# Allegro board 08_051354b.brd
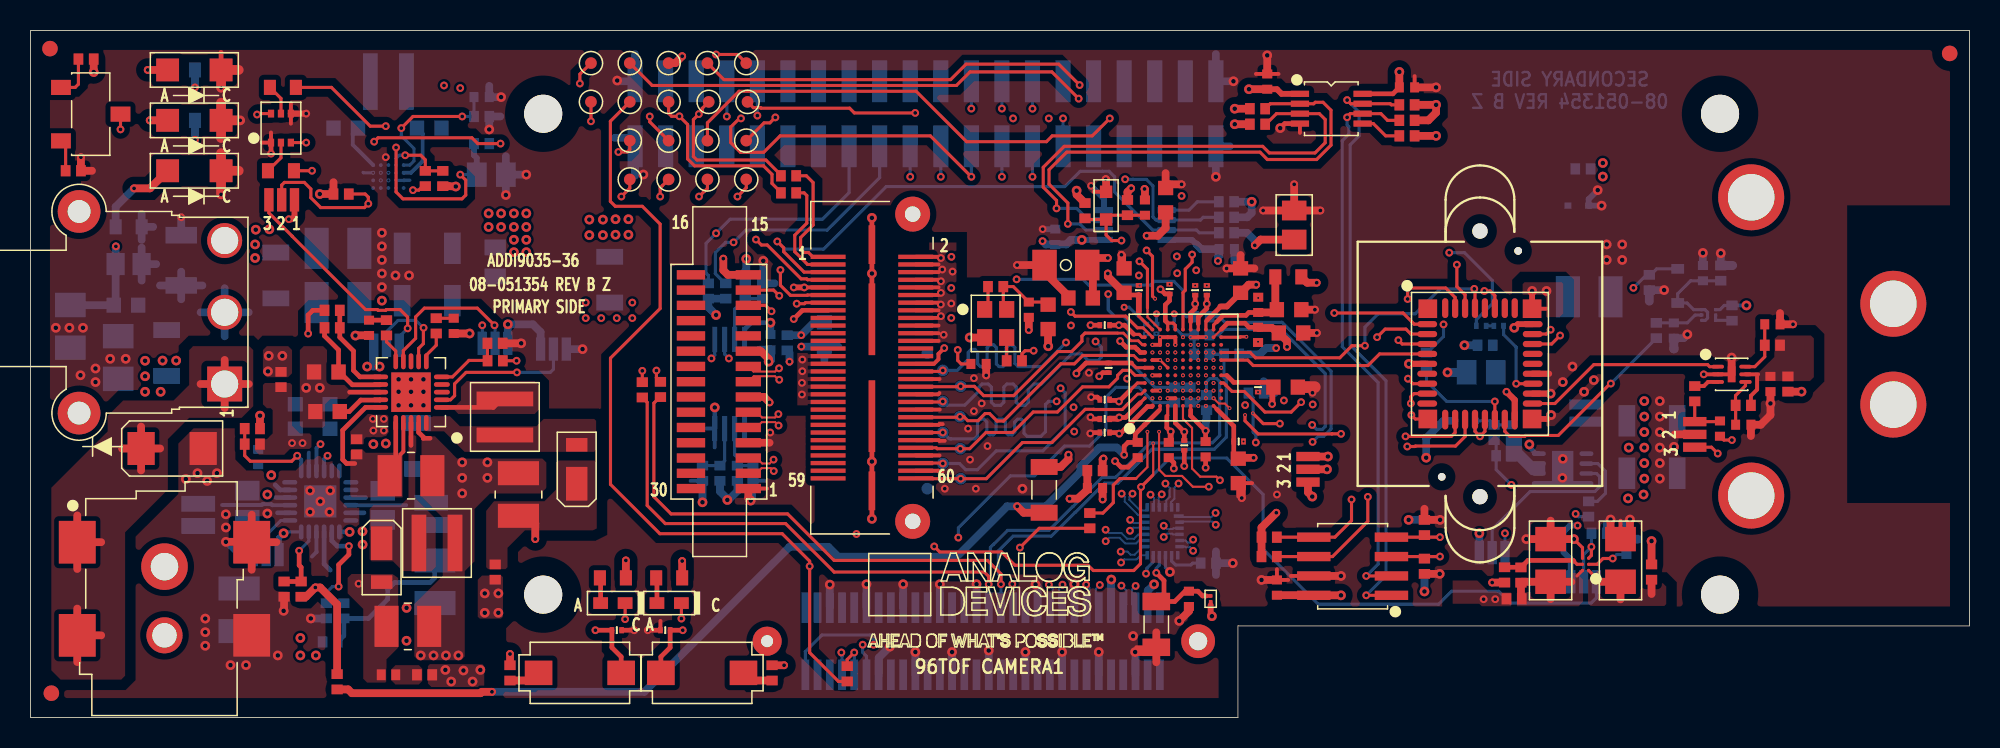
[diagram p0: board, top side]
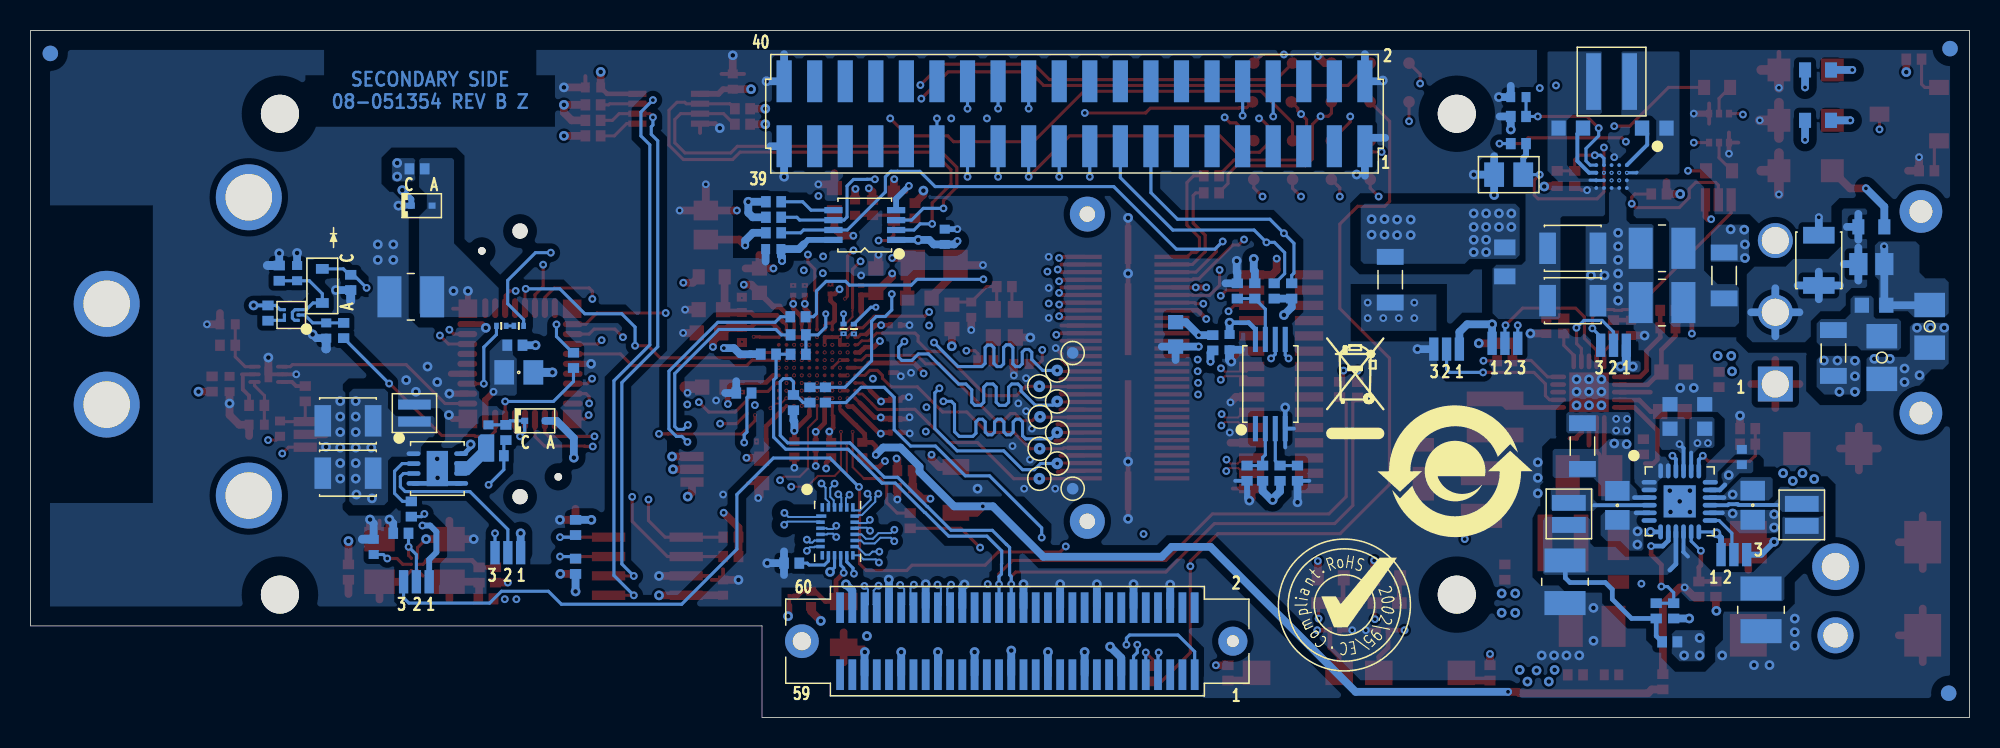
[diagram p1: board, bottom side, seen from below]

Outline 126.86 x 45 mm; copper layers: TOP, L2_GND, L3_SIG, L4_GND, L5_PWR, L6_PWR, L7_GND, L8_SIG, L9_GND, BOTTOM. Coordinates in mm from the lower left corner of the outline.
Outline path: 0,45 126.86,45 126.86,6 79,6 79,0 0,0 0,45

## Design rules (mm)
constraint set DEFAULT: min track width 0.203, pair gap 0.203
net group DP1: nets CCDGNDA CCDINA
net group CLK_DATA_MISIPI: nets CLK_N CLK_P DATA0_N DATA0_P DATA1_N DATA1_P
net group LD1_LD4: nets LD1 LD2 LD3 LD4
net group MIPI_DATA_P3_CONN: nets MIPI_CSI1_CLK_M MIPI_CSI1_CLK_P MIPI_CSI1_DATA0_M MIPI_CSI1_DATA0_P MIPI_CSI1_DATA1_M MIPI_CSI1_DATA1_P
net group RPI_DATA_P1_CONN: nets RPI_CLKN RPI_CLKP RPI_DATA0N RPI_DATA0P RPI_DATA1N RPI_DATA1P
net group TAL1_TAL4: nets TAL1 TAL2 TAL3 TAL4

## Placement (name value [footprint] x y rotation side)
A1  ADA4800_PRELIM  [UQFN6_1_6X1_6PAD0_5X1_05]  111.3 22.48 270 top
C1  2.2UF  [C1206]  73.66 6.1 90 top
C2  0.1uF  [C0201]  73.67 25.45 270 bottom
C3  4.7UF  [C0805H60]  14.18 13.91 90 bottom
C4  4.7UF  [C0805H60]  23.04 13.89 270 bottom
C5  0.1UF  [C0402]  65.31 26.71 270 top
C6  4.7uF  [C0603]  74.27 33.88 90 top
C7  0.1UF  [C0402]  69.64 15.03 0 top
C8  0.1uF  [C0201]  72.99 25.45 270 bottom
C9  0.1UF  [C0402]  14.89 17.06 270 bottom
C10  4.7uF  [C0603]  68.7 27.48 180 top
C11  4.7uF  [C0603]  79.17 28.62 90 top
C12  4.7uF  [C0603]  82.47 25.19 0 top
C13  1UF  [C0805H53]  82.68 32.26 90 top
C14  0.1uF  [C0201]  70.53 22.9 270 top
C15  0.1UF  [C0402]  80.31 25.06 270 top
C16  0.1uF  [C0201]  70.28 20.82 180 top
C17  0.1uF  [C0201]  76.96 27.98 90 top
C18  1000PF  [C0402]  107.51 25.35 270 bottom
C19  0.1uF  [C0201]  75.49 17.82 270 top
C20  4.7uF  [C0603]  82.34 26.71 180 top
C21  0.1UF  [C0402]  110.54 18.92 270 top
C22  0.1uF  [C0201]  80.31 21.63 270 top
C23  0.1uF  [C0201]  70.28 18.66 180 top
C24  0.1UF  [C0402]  62.02 23.16 0 top
C25  0.1uF  [C0201]  79.04 18.08 0 top
C26  0.1uF  [C0201]  70.28 25.7 180 top
C27  0.1UF  [C0402]  80.32 27.03 90 top
C28  0.1uF  [C0201]  72.51 27.98 90 top
C29  0.1UF  [C0402]  113.97 25.76 180 top
C30  0.01uF  [C0402]  109.42 29.11 90 bottom
C31  0.1uF  [C0201]  70.28 19.55 180 top
C32  22UF  [C1210H106]  25.95 30.73 180 bottom
C33  0.1UF  [C0402]  76.88 17.57 270 top
C34  22UF  [C1210H106]  25.95 27.3 180 bottom
C35  1000PF  [C0402]  29.51 40.64 0 bottom
C36  0.1uF  [C0603]  20.62 38.61 0 bottom
C37  0.1uF  [C0603]  26.08 38.61 0 bottom
C38  10uF  [C1210-2]  20.11 27.18 0 bottom
C39  10uF  [C1210-2]  20.11 30.73 0 bottom
C40  1UF  [C0805H53]  30.15 35.56 0 bottom
C41  10uF  [C1210-2]  24.89 15.84 0 top
C42  22UF  [C1210H106]  9.86 29.95 90 bottom
C43  1UF  [C0603]  19.35 22.63 180 top
C44  22UF  [C1210H106]  106.09 16 0 bottom
C45  1UF  [C0603]  19.59 19.72 90 bottom
C46  1UF  [C0603]  17.32 19.72 90 bottom
C47  10uF  [C1210-2]  26.46 8.89 270 bottom
C48  10uF  [C1210-2]  13.64 7.05 270 bottom
C49  10UF  [C1206H71]  2.6 25.62 90 bottom
C50  10UF  [C1206H71]  5.73 23.58 90 bottom
C51  10uF  [C1210-2]  101.98 27.56 0 bottom
C52  0.1UF  [C0402]  48.41 24.59 270 bottom
C53  1uF  [C0402]  72.44 17.52 90 top
C54  1uF  [C0402]  74.47 17.52 270 top
C55  0.10UF  [C0508H28]  101.74 19.94 90 bottom
C56  10NF  [C0402]  75.79 7.77 90 top
C57  1uF  [C0402]  72.91 33.4 270 top
C58  0.1uF  [C0201]  76.2 27.98 90 top
C59  0.033uF  [C0402]  96.9 18.67 90 bottom
C60  0.1uF  [C0201]  74.52 28.06 90 top
C61  10UF  [C1206H71]  67.74 29.64 180 top
C62  0.1UF  [C0402]  113.84 21.84 90 top
C63  0.1UF  [C0402]  80.91 41.66 270 top
C64  22UF  [C1210H106]  106.09 19.43 0 bottom
C65  0.1UF  [C0402]  112.06 19.18 0 top
C66  1UF  [C0603]  19.43 20.04 180 top
C67  0.1uF  [C0603]  51.94 25.1 90 bottom
C68  0.1UF  [C0402]  90.06 41.27 0 top
C69  0.1UF  [C0402]  81.55 8.51 270 top
C70  0.1UF  [C0402]  67.04 31.49 270 bottom
C71  10uF  [C1210-2]  24.68 5.97 0 top
C72  0.047UF  [C0402]  27.69 25.65 270 top
C73  0.01uF  [C0201]  96.06 25.65 0 bottom
C74  0.047UF  [C0402]  22.14 25.53 270 top
C75  0.1UF  [C0402]  78.26 30.68 0 bottom
C76  4.7UF  [C0805H60]  94.92 22.61 180 bottom
C77  0.01uF  [C0603]  79.02 16.15 90 top
C78  10uF  [C1210-2]  31.92 14.61 90 top
C79  2.2uF  [C1206H37]  104.03 10.29 90 top
C80  1000PF  [C0402]  104.41 11.18 90 bottom
C81  2.2uF  [C1206H37]  99.45 10.29 90 top
C82  0.01uF  [C0603]  82.12 21.64 180 top
C83  0.01uF  [C0603]  71.55 28.62 270 top
C84  0.01uF  [C0201]  38.35 5.71 0 top
C85  0.01uF  [C0201]  41.53 5.71 180 top
D1  SMAJ5.0A  [DO214AC]  9.26 17.62 0 top
D4  RB521S30T1G  [SOD523]  93.85 19.43 180 bottom
D5  1SS355VMTE-17  [SOD323-4]  107.77 28.27 270 bottom
D6  RB521S30T1G  [SOD523]  101.27 33.53 180 bottom
D8  DFLS240-7  [DSML110W70H39]  22.97 10.47 270 top
D9  DFLS240-7  [DSML110W70H39]  35.73 16.26 90 top
DS1  CMD15-21UGC/TR8 (green)  [LED1206]  10.71 35.81 180 top
DS2  CMD15-21UGC/TR8 (green)  [LED1206]  10.71 39.12 180 top
DS3  CMD15-21UGC/TR8 (green)  [LED1206]  10.71 42.42 180 top
DS4  APT1608LVBC/D  [LED0603]  38.1 7.49 180 top
DS5  APT1608LSECK/J3-PRV  [LED0603]  41.78 7.49 180 top
E1  60OHM AT 100MEGHZ  [L0603]  66.57 26.24 270 top
E2  22OHM AT 100MEGHZ  [L0805]  6.42 29.7 180 bottom
E3  30OHM  [L0603]  6.24 27.01 0 bottom
E4  470OHMS AT 100MEGHZ  [L0402]  23.42 2.79 0 top
E5  22OHM AT 100MHZ  [L01005]  77.21 7.77 90 top
GND7  TESTPAD  [TPSMC30]  58.67 14.99 270 bottom
GND8  TESTPAD  [TPSMC30]  58.67 23.88 270 bottom
JP1  3PIN_SOLDER_JUMPER  [JPRSLD03]  83.58 16.26 270 top
JP2  3PIN_SOLDER_JUMPER  [JPRSLD03]  95.63 10.79 0 bottom
JP3  3PIN_SOLDER_JUMPER  [JPRSLD03]  16.43 33.91 180 top
JP4  3PIN_SOLDER_JUMPER  [JPRSLD03]  15.41 10.67 180 bottom
JP5  3PIN_SOLDER_JUMPER  [JPRSLD03]  108.89 18.54 270 top
JP6  3PIN_SOLDER_JUMPER  [JPRSLD03]  30.39 24.51 180 bottom
JP7  3PIN_SOLDER_JUMPER  [JPRSLD03]  23.29 24.38 0 bottom
JP8  3PIN_SOLDER_JUMPER  [JPRSLD03]  34.21 24.13 0 bottom
JP9  3PIN_SOLDER_JUMPER  [JPRSLD03]  101.61 8.89 0 bottom
L1  2.2uH  [LSMSQ157H83_A]  23.41 41.66 180 bottom
L2  1uH  [LSML75W79H39]  10.97 13.27 90 bottom
L3  1uH  [LSML75W79H39]  26.21 13.34 90 bottom
L8  4.7uH  [LSMSQ157H122]  26.59 11.43 180 top
L9  4.7uH  [LSMSQ157H122]  31.03 19.68 270 top
LD1  TESTPAD  [TPSMC30]  60.86 15.64 270 bottom
LD2  TESTPAD  [TPSMC30]  60.84 17.61 270 bottom
LD3  TESTPAD  [TPSMC30]  60.81 19.7 270 bottom
LD4  TESTPAD  [TPSMC30]  60.86 21.69 270 bottom
LD_EN1  0  [R0402]  49.59 35.48 180 top
LD_EN2  0  [R0402]  49.59 34.37 180 top
NOREF  -  []  0 45 0 top
NOREF#2  -  []  -176.26 -281.43 0 top
NOREF#3  -  []  0 0 0 top
NOREF#4  -  []  79 0 0 top
NOREF#5  -  []  70.12 -90.11 0 top
NOREF#6  -  [unnamed#2]  110.54 39.55 0 top
NOREF#7  -  []  -176.26 -281.43 0 top
NOREF#8  -  [unnamed#2]  1.27 43.81 90 top
NOREF#9  -  []  -176.26 -281.43 0 top
NOREF#10  -  []  -10.16 55.16 0 top
NOREF#11  -  []  8.76 5.38 0 top
NOREF#12  -  []  57.78 56.26 0 top
NOREF#13  -  []  281.83 80.52 0 top
NOREF#14  -  [unnamed#2]  33.54 39.55 0 top
NOREF#15  -  [unnamed#2]  33.54 8.05 0 top
NOREF#16  -  [unnamed#3]  94.83 23.16 270 top
NOREF#17  -  []  79 0 90 top
NOREF#18  -  []  0 0 0 top
NOREF#19  -  []  79 6 0 top
NOREF#20  -  [unnamed#2]  125.57 43.5 90 top
NOREF#21  -  []  8.76 5.38 0 top
NOREF#22  -  []  126.86 6 0 top
NOREF#23  -  []  -125.84 190.5 0 top
NOREF#24  -  []  332.25 207.39 0 top
NOREF#25  -  [unnamed#2]  121.88 27.1 90 top
NOREF#26  -  []  137.02 55.16 0 top
NOREF#27  -  [unnamed#2]  121.88 20.5 90 top
NOREF#28  -  [unnamed#2]  110.54 8.05 0 top
NOREF#29  -  []  0 45 0 top
NOREF#30  -  [unnamed#2]  1.36 1.59 90 top
NOREF#31  -  [unnamed#2]  112.58 14.54 90 top
NOREF#32  -  [unnamed#2]  112.58 34.08 90 top
NOREF#33  -  [unnamed#2]  1.27 43.81 90 bottom
NOREF#34  -  [unnamed#2]  1.36 1.59 90 bottom
NOREF#35  -  []  -10.16 -10.16 180 bottom
NOREF#36  -  []  40.39 18.29 180 bottom
NOREF#37  -  [unnamed#2]  125.57 43.5 90 bottom
NOREF#38  -  []  79 6 0 bottom
NOREF#39  -  []  0 0 90 bottom
NOREF#40  -  []  0 45 0 bottom
NOREF#41  -  []  126.86 45 270 bottom
NOREF#42  -  []  126.86 6 180 bottom
NOREF#43  -  []  33.66 16.13 180 bottom
NOREF#44  -  []  40.89 7.37 180 bottom
NOREF#45  -  []  79 0 180 bottom
P1  1-1734248-5  [CNTE1-1734248-5]  45.09 22 90 top
P3  61083-063402LF  [CNFCI61083-063402]  62.29 5 0 bottom
P4  87759-4014  [CNSMMHDR2X20L1571W157H272]  58.55 39.55 0 bottom
P21  QSH-030-01-L-D-A  [CNHDR2X30H202]  55.05 22.91 270 top
P31  PJ-002AH-SMT-TR  [CNCUI-PJ-002A_A]  8.76 7.78 0 top
Q1  DST847BPDP6-7  [SOT-963]  109.8 26.37 90 bottom
Q2  BC847CDW1T1G  [SC70]  16.38 38.61 0 top
R1  10K  [R0402]  63.15 28.22 0 top
R2  49.9  [R0402]  80.19 21.25 180 bottom
R3  0  [R0402]  76.63 25.06 180 bottom
R4  0  [R1206]  66.32 14.91 90 top
R5  0  [R0402]  101.94 13.66 90 bottom
R6  0  [R0402]  76.63 23.79 180 bottom
R7  47  [R0402]  106.37 25.35 90 bottom
R8  0  [R0402]  30.4 9.53 270 top
R9  0  [R0402]  114.98 21.84 90 top
R10  0  [R0603]  82.29 28.86 180 top
R11  0  [R0805]  30.4 29.84 270 bottom
R12  0  [R0402]  25.83 35.31 90 top
R13  100K  [R0402]  29.51 39.37 0 bottom
R14  10K  [R0402]  20.32 34.29 180 top
R15  100K  [R0402]  29.51 37.59 180 bottom
R16  0  [R1206]  16.05 28.96 90 bottom
R17  0  [R1206]  25.32 17.78 270 bottom
R18  10K  [R0402]  14.51 18.92 180 top
R19  26.7K  [R0402]  14.51 17.91 0 top
R20  29.4K  [R0402]  19.35 6.99 270 bottom
R21  95.3K  [R0402]  20.49 6.99 270 bottom
R22  0  [R0402]  20.06 2.34 270 top
R23  19.1K  [R0402]  16.59 8.41 270 top
R24  0  [R0402]  78.25 33.78 180 bottom
R25  0  [R0402]  26.97 35.31 270 top
R26  1K  [R0402]  111.32 26.49 270 bottom
R27  5.1K  [R0402]  110.59 29.11 90 bottom
R28  0  [R0402]  74.85 21.13 90 bottom
R29  1MEG  [R0402]  105.91 28.5 270 bottom
R30  115K  [R0402]  17.7 8.41 270 top
R31  120K  [R0402]  113.97 24.38 0 top
R32  0  [R0402]  19.6 4.95 180 bottom
R33  249K  [R0402]  112.06 20.45 0 top
R34  0  [R0402]  16.38 22.14 90 top
R35  0  [R0402]  49.51 24.54 270 bottom
R36  0  [R0402]  2.79 35.81 180 top
R37  220  [R0603]  38.1 9.14 0 top
R38  10K  [R0402]  102.63 12.06 0 bottom
R39  0  [R1206]  37.9 28.68 270 bottom
R40  49.9  [R0402]  96.39 17.14 0 bottom
R41  0  [R0402]  75.87 21.13 90 bottom
R42  0  [R0402]  95.76 18.67 270 bottom
R43  10K  [R0402]  76.94 20.63 90 bottom
R44  0  [R0402]  21.34 17.73 270 top
R45  10K  [R0402]  78.58 23.8 180 bottom
R46  147K  [R0402]  19.73 25.53 0 top
R47  0  [R0402]  45.11 16 270 bottom
R48  137K  [R0402]  30.39 24.51 0 top
R49  1.2MEG  [R0402]  19.73 26.67 180 top
R50  24.9K  [R0402]  26.54 25.65 90 top
R51  6.8K  [R0402]  23.29 25.53 90 top
R52  2.37MEG  [R0402]  30.4 23.37 0 top
R53  0  [R0402]  25.78 2.79 0 top
R54  0  [R0402]  43.96 16 90 bottom
R55  0  [R0402]  46.76 27.94 90 bottom
R56  0  [R0402]  106.06 9.53 270 top
R57  14.3K  [R0402]  96.44 9.34 270 top
R58  93.1K  [R0402]  97.51 9.33 270 top
R59  0  [R0402]  97.07 7.77 180 top
R60  0  [R0402]  47.9 27.94 270 bottom
R61  22K  [R0402]  44.34 27.94 270 bottom
R62  0  [R0402]  46.25 16 270 bottom
R63  0  [R0402]  47.27 16 90 bottom
R64  22K  [R0402]  45.49 27.94 270 bottom
R65  0  [R0402]  69.64 16.17 0 top
R66  4.7  [R0402]  91.33 23.39 270 bottom
R67  22K  [R0402]  80.28 38.86 180 top
R68  22K  [R0402]  80.28 39.88 180 top
R69  4.7  [R0201]  94.92 25.65 0 bottom
R70  0  [R0402]  101.57 35.94 0 bottom
R71  0  [R0402]  95.17 24.38 180 bottom
R72  45.3K  [R0402]  68.99 33.2 90 top
R73  45.3K  [R0402]  71.77 33.4 270 top
R74  4.7K  [R0402]  90.06 39.12 180 top
R75  300  [R0603]  41.78 9.14 180 top
R76  0  [R0402]  108.89 21.21 270 top
R77  100K  [R0402]  31.37 2.92 270 top
R78  10K  [R0603]  16.38 35.81 180 top
R79  10K  [R0603]  16.51 41.27 180 top
R80  100K  [R0402]  48.51 2.92 270 top
R82  4.7K  [R0402]  90.06 40.13 180 top
R86  10K  [R0402]  81.04 11.81 0 top
R87  10K  [R0402]  81.04 10.54 0 top
R88  0  [R0402]  76.65 26.25 0 bottom
R89  0  [R0402]  69.31 12.89 270 top
R90  0  [R0402]  77.06 10.11 180 bottom
R91  0  [R0402]  3.63 43.13 0 top
R93  4.7K  [R0402]  78.25 32.77 0 bottom
R94  4.7K  [R0402]  78.25 31.75 0 bottom
R95  0  [R1206]  8.9 23.88 270 bottom
R98  0  [R0402]  40.03 21.46 90 top
R100  150  [R0603]  6.42 32.14 0 bottom
R101  0  [R0402]  90.06 38.1 0 top
R102  0  [R0402]  91.2 12.45 90 bottom
R103  0  [R0402]  91.2 12.45 270 top
R104  680  [R0603]  9.91 39.12 180 bottom
R105  0  [R0402]  91.2 9.91 270 bottom
R106  0  [R0402]  91.2 9.91 90 top
R108  220  [R0603]  9.91 42.42 0 bottom
R109  0  [R0402]  41.21 21.49 90 top
R110  22  [R0402]  64.36 23.37 0 top
R113  22  [R0402]  53.43 2.86 90 top
RT1  100K  [R0603H35]  70.37 33.53 270 top
S1  CAS-120TB  [SWSML213W98H98]  3.94 39.52 270 top
S2  MS12ASW30  [SWTHL500W272H280]  12.7 21.84 90 top
S3  SKQMBBE010  [SWSML236W138H197]  35.94 2.92 0 top
S4  SKQMBBE010  [SWSML236W138H197]  43.94 2.92 0 top
TAL1  TESTPAD  [TPSMC30]  59.69 16.64 270 bottom
TAL2  TESTPAD  [TPSMC30]  59.69 18.67 270 bottom
TAL3  TESTPAD  [TPSMC30]  59.69 20.7 270 bottom
TAL4  TESTPAD  [TPSMC30]  59.69 22.73 270 bottom
TP1  TESTPAD  [TPSMC30]  46.91 40.33 0 top
TP2  TESTPAD  [TPSMC30]  46.83 37.79 0 top
TP3  TESTPAD  [TPSMC30]  46.83 42.87 0 top
TP4  TESTPAD  [TPSMC30]  41.75 35.25 0 top
TP5  TESTPAD  [TPSMC30]  39.21 35.25 0 top
TP6  TESTPAD  [TPSMC30]  44.29 37.79 0 top
TP7  TESTPAD  [TPSMC30]  41.75 37.79 0 top
TP8  TESTPAD  [TPSMC30]  36.67 40.33 0 top
TP9  TESTPAD  [TPSMC30]  36.67 42.87 270 top
TP10  TESTPAD  [TPSMC30]  39.21 37.79 0 top
TP11  TESTPAD  [TPSMC30]  46.83 35.25 0 top
TP12  TESTPAD  [TPSMC30]  44.29 35.25 0 top
TP13  TESTPAD  [TPSMC30]  39.21 42.87 0 top
TP14  TESTPAD  [TPSMC30]  44.29 42.87 0 top
TP15  TESTPAD  [TPSMC30]  39.21 40.33 0 top
TP16  TESTPAD  [TPSMC30]  41.75 40.33 0 top
TP17  TESTPAD  [TPSMC30]  44.37 40.33 0 top
TP18  TESTPAD  [TPSMC30]  41.75 42.87 0 top
U1  MN34906BL  [QFN38_7_8X7_4]  94.83 23.16 270 top
U2  ADP2505ACBZ  [WLCSP20_A]  23.41 35.43 0 bottom
U3  ADP5023ACPZ  [QFN24_4X4_PAD2_1X2_1]  18.96 14.16 270 bottom
U4  ADDI9036BCBZRL  [WLCSP117_A]  75.4 22.91 0 top
U5  AT24CM01-XHM-B  [TSSOP8]  45.74 21.84 180 bottom
U6  FAN3121TMPX  [MLP8_3X3_PAD2_3X1_4]  100.24 16.31 270 bottom
U7  FSA642UMX  [QFN24_3_4X2_5]  74.05 12.19 270 bottom
U8  PCA9517ADMR2G  [MSOP8_ALT]  85.1 39.88 270 top
U9  PCA9517ADMR2G  [MSOP8_ALT]  72.28 32.26 90 bottom
U10  ADP5071ACPZ  [QFN20_4X4_PAD2_6X2_6]  24.89 21.31 90 top
U12  ADP7112ACBZ-1.2-R7  [WLCSP6_B]  101.74 10.03 90 top
U13  ADT7410TRZ  [SO8]  86.5 9.91 90 top
Y1  45.000000MEGHZ  [YSML98W79H35]  63.15 25.81 270 top

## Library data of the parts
A1 = ADA4800_PRELIM: User Part Number: UPN; Tolerance: N/A; alternate symbols: (); part number: ADA4800_PRELIM_SM-ADA4800_PRELIM,E012130,UQFN6_1_6X1_6PAD0_5X1_05; tolerance: N/A
C1 = CAP: User Part Number: UPN; Tolerance: 10; alternate symbols: (); part number: CAP_SM-2.2UF,16V,10,E033858,C1206; tolerance: 10
C2 C8 C14 C16 C17 C19 C22 C23 C25 C26 C28 C31 C58 C60 = CAP: Tolerance: 10; User Part Number: UPN; alternate symbols: (); part number: CAP_SM-0.1UF,6.3V,10,E011567,C0201; tolerance: 10
C3 C4 C76 = CAP: Tolerance: 10; User Part Number: UPN; alternate symbols: (); part number: CAP_SM-4.7UF,25V,10,E033894,C0805H60; tolerance: 10
C5 C7 C9 C15 C21 C24 C27 C29 C33 C52 C62 C63 C65 C68-C70 C75 = CAP: User Part Number: UPN; Tolerance: 10; alternate symbols: (); part number: CAP_SM-0.1UF,16V,10,E028141,C0402; tolerance: 10
C6 C10 C12 C20 = CAP: User Part Number: UPN; Tolerance: 10; alternate symbols: (); part number: CAP_SM-4.7UF,16V,10,E022190,C0603; tolerance: 10
C11 = CAP: User Part Number: UPN; Tolerance: 10; alternate symbols: C0603L; part number: CAP_SM-4.7UF,16V,10,E022190,C0603; tolerance: 10
C13 = CAP: Tolerance: 10; User Part Number: UPN; alternate symbols: C0805L; part number: CAP_SM-1UF,35V,10,E035216,C0805H53; tolerance: 10
C18 = CAP: User Part Number: UPN; Tolerance: 10; alternate symbols: (); part number: CAP_SM-1000PF,50V,10,E020689,C0402; tolerance: 10
C30 = CAP: User Part Number: UPN; Tolerance: 5; alternate symbols: (C0402L_ALT); part number: CAP_SM-0.01UF,25V,5,E020410,C0402; tolerance: 5
C32 C34 C42 C44 C64 = CAP: Tolerance: 10; User Part Number: UPN; alternate symbols: (); part number: CAP_SM-22UF,25V,10,E025745,C1210H106; tolerance: 10
C35 C80 = CAP: User Part Number: UPN; Tolerance: 10; alternate symbols: (); part number: CAP_SM-1000PF,25V,10,E025706,C0402; tolerance: 10
C36 C37 = CAP: User Part Number: UPN; Tolerance: 10; alternate symbols: (); part number: CAP_SM-0.1UF,50V,10,E011865,C0603; tolerance: 10
C38 C39 C41 C47 C48 C51 C71 C78 = CAP: Tolerance: 10; User Part Number: UPN; alternate symbols: (); part number: CAP_SM-10UF,50V,10,E022361,C1210-2; tolerance: 10
C40 = CAP: Tolerance: 10; User Part Number: UPN; alternate symbols: (); part number: CAP_SM-1UF,50V,10,E033068,C0805H53; tolerance: 10
C43 C45 C46 C66 = CAP: User Part Number: UPN; Tolerance: 10; alternate symbols: (); part number: CAP_SM-1UF,25V,10,E025743,C0603; tolerance: 10
C49 C50 C61 = CAP: Tolerance: 10; User Part Number: UPN; alternate symbols: (); part number: CAP_SM-10UF,25V,10,E022363,C1206H71; tolerance: 10
C53 C54 C57 = CAP: User Part Number: UPN; Tolerance: 10; alternate symbols: (); part number: CAP_SM-1UF,6.3V,10,E011561,C0402; tolerance: 10
C55 = CAP: Tolerance: 20; User Part Number: UPN; alternate symbols: (); part number: CAP_SM-0.10UF,25V,20,E025747,C0508H28; tolerance: 20
C56 = CAP: User Part Number: UPN; Tolerance: 10; alternate symbols: (); part number: CAP_SM-10NF,25V,10,E033465,C0402; tolerance: 10
C59 = CAP: User Part Number: UPN; Tolerance: 10; alternate symbols: (); part number: CAP_SM-0.033UF,50V,10,E019776,C0402; tolerance: 10
C67 = CAP: User Part Number: UPN; Tolerance: 10; alternate symbols: (); part number: CAP_SM-0.1UF,16V,10,E011547,C0603; tolerance: 10
C72 C74 = CAP: User Part Number: UPN; Tolerance: 10; alternate symbols: (); part number: CAP_SM-0.047UF,25V,10,E025704,C0402; tolerance: 10
C73 C84 C85 = CAP: Tolerance: 10; User Part Number: UPN; alternate symbols: (); part number: CAP_SM-0.01UF,10V,10,E007201,C0201; tolerance: 10
C77 C82 C83 = CAP: User Part Number: UPN; Tolerance: 5; alternate symbols: (); part number: CAP_SM-0.01UF,25V,5,E012400,C0603; tolerance: 5
C79 C81 = CAP: Tolerance: 10; User Part Number: UPN; alternate symbols: (); part number: CAP_SM-2.2UF,50V,10,E020593,C1206H37; tolerance: 10
D1 = DIO: User Part Number: UPN; Tolerance: 5; alternate symbols: (); part number: DIO_SM-SMAJ5.0A,N/A,5,E020098,DO214AC; tolerance: 5
D4 D6 = DIO: Tolerance: N/A; User Part Number: UPN; alternate symbols: (); part number: DIO_SM-RB521S30T1G,30V,N/A,E011362,SOD523; tolerance: N/A
D5 = DIO: Tolerance: N/A; User Part Number: UPN; alternate symbols: (); part number: DIO_SM-1SS355VMTE-17,80V,N/A,E027000,SOD323-4; tolerance: N/A
D8 D9 = DIOSCHOTTKY: Tolerance: N/A; User Part Number: UPN; alternate symbols: (); part number: DIOSCHOTTKY_SM-DFLS240-7,40V,N/A,E019969,DSML110W70H39; tolerance: N/A
DS1-DS3 = DIOLED: Tolerance: N/A; User Part Number: UPN; alternate symbols: (); part number: DIOLED_SM-CMD15-21UGC/TR8 (GREEN),2.1V,N/A,E012771,LED1206; tolerance: N/A
DS4 = DIOLED: Tolerance: N/A; User Part Number: UPN; alternate symbols: (); part number: DIOLED_SM-APT1608LVBC/D,2.65V,N/A,E033357,LED0603; tolerance: N/A
DS5 = DIOLED: Tolerance: N/A; User Part Number: UPN; alternate symbols: (); part number: DIOLED_SM-APT1608LSECK/J3-PRV,1.8V,N/A,E030191,LED0603; tolerance: N/A
E1 = FERRITE: User Part Number: UPN; Tolerance: 25; alternate symbols: (); part number: FERRITE_SM-60OHM AT 100MEGHZ,25,E029937,L0603; tolerance: 25
E2 = FERRITE: User Part Number: UPN; Tolerance: 25; alternate symbols: (); part number: FERRITE_SM-22OHM AT 100MEGHZ,25,E029266,L0805; tolerance: 25
E3 = FERRITE: User Part Number: UPN; Tolerance: 10OHM; alternate symbols: (); part number: FERRITE_SM-30OHM,10OHM,E027025,L0603; tolerance: 10OHM
E4 = FERRITE: User Part Number: UPN; Tolerance: 25; alternate symbols: (); part number: FERRITE_SM-470OHMS AT 100MEGHZ,25,E027133,L0402; tolerance: 25
E5 = FERRITE: User Part Number: UPN; Tolerance: 25; alternate symbols: (); part number: FERRITE_SM-22OHM AT 100MEGHZ,25,E034118,L01005; tolerance: 25
GND7 GND8 LD1-LD4 TAL1-TAL4 TP1-TP18 = NCTESTPAD: Tolerance: N/A; User Part Number: UPN; alternate symbols: (); part number: NCTESTPAD_SM-TESTPAD,E012884,TPSMC30; tolerance: N/A
JP1-JP9 = NC3P_JMPR: Tolerance: N/A; User Part Number: UPN; alternate symbols: (); part number: NC3P_JMPR_SM-3PIN_SOLDER_JUMPER,E005606,JPRSLD03; tolerance: N/A
L1 = IND: User Part Number: UPN; Tolerance: 20; alternate symbols: (); part number: IND_SM-2.2UH,20,E021261,LSMSQ157H83_A; tolerance: 20
L2 L3 = IND: Tolerance: 20; User Part Number: UPN; alternate symbols: (); part number: IND_SM-1UH,20,E015752,LSML75W79H39; tolerance: 20
L8 L9 = IND: User Part Number: UPN; Tolerance: 20; alternate symbols: (); part number: IND_SM-4.7UH,20,E013623,LSMSQ157H122; tolerance: 20
LD_EN1 LD_EN2 = RESJMPRSHRT: User Part Number: UPN; Tolerance: N/R; alternate symbols: (); part number: RESJMPRSHRT_SM-0,E003438,N/RW,N/R,R0402; tolerance: N/R
P1 = CN30P_V2: User Part Number: UPN; Tolerance: N/A; alternate symbols: (); part number: CN30P_V2_SM-1-1734248-5,E033905,CNTE1-1734248-5; tolerance: N/A
P3 = CN60P_ODD_EVEN: User Part Number: UPN; Tolerance: N/A; alternate symbols: (); part number: CN60P_ODD_EVEN_SM-61083-063402LF,E033470,CNFCI61083-063402; tolerance: N/A
P4 = CN40P_V2: User Part Number: UPN; Tolerance: N/A; alternate symbols: (); part number: CN40P_V2_SM-87759-4014,E033485,CNSMMHDR2X20L1571W157H272; tolerance: N/A
P21 = CN60P_ODD_EVEN_4GND: User Part Number: UPN; Tolerance: N/A; alternate symbols: (CNHDR2X30H202_ALT); part number: CN60P_ODD_EVEN_4GND_SM-QSH-030-01-L-D-A,E014016,CNHDR2X30H202; tolerance: N/A
P31 = CN4P_V6: User Part Number: UPN; Tolerance: N/A; alternate symbols: (); part number: CN4P_V6_SM-PJ-002AH-SMT-TR,E022246,CNCUI-PJ-002A_A; tolerance: N/A
Q1 = TRANNPN_PNP: Tolerance: N/A; User Part Number: UPN; alternate symbols: (); part number: TRANNPN_PNP_SM-DST847BPDP6-7,E028630,SOT-963; tolerance: N/A
Q2 = TRANBC84XXDW: Tolerance: N/A; User Part Number: UPN; alternate symbols: (); part number: TRANBC84XXDW_SM-BC847CDW1T1G,E011779,SC70; tolerance: N/A
R1 R14 R18 R38 R43 R45 = RES: User Part Number: UPN; Tolerance: 1; alternate symbols: (R0402L,R0402L_ALT); part number: RES_SM-10K,E003751,1/10W,1,R0402; tolerance: 1
R2 R40 = RES: User Part Number: UPN; Tolerance: 0.1; alternate symbols: (R0402L,R0402L_ALT); part number: RES_SM-49.9,E005976,1/16W,0.1,R0402; tolerance: 0.1
R3 R5 R6 R8 R9 R12 R22 R24 R25 R28 R32 R34-R36 R41 R42 R44 R47 R54-R56 R59 R60 R62 R63 R65 R70 R71 R76 R88-R91 R98 R101-R103 R105 R106 R109 = RES: User Part Number: UPN; Tolerance: 5; alternate symbols: (R0402L,R0402L_ALT); part number: RES_SM-0,E003438,N/A,5,R0402; tolerance: 5
R4 R16 R17 R39 R95 = RES: User Part Number: UPN; Tolerance: N/A; alternate symbols: (); part number: RES_SM-0,E014206,1/2W,N/A,R1206; tolerance: N/A
R7 = RES: User Part Number: UPN; Tolerance: 5; alternate symbols: (R0402L); part number: RES_SM-47,E017767,1/10W,5,R0402; tolerance: 5
R10 = RES: User Part Number: UPN; Tolerance: 5; alternate symbols: (R0603L); part number: RES_SM-0,E006826,1/10W,5,R0603; tolerance: 5
R11 = RES: User Part Number: UPN; Tolerance: N/A; alternate symbols: (R0805L); part number: RES_SM-0,E004152,1/10W,N/A,R0805; tolerance: N/A
R13 R15 R77 R80 = RES: User Part Number: UPN; Tolerance: 1; alternate symbols: (R0402L,R0402L_ALT); part number: RES_SM-100K,E003796,1/16W,1,R0402; tolerance: 1
R19 = RES: User Part Number: UPN; Tolerance: 1; alternate symbols: (R0402L); part number: RES_SM-26.7K,E012976,1/16W,1,R0402; tolerance: 1
R20 = RES: User Part Number: UPN; Tolerance: 1; alternate symbols: (R0402L); part number: RES_SM-29.4K,E025783,1/10W,1,R0402; tolerance: 1
R21 = RES: User Part Number: UPN; Tolerance: 1; alternate symbols: (R0402L); part number: RES_SM-95.3K,E006343,1/16W,1,R0402; tolerance: 1
R23 = RES: User Part Number: UPN; Tolerance: 1; alternate symbols: (R0402L); part number: RES_SM-19.1K,E025171,1/10W,1,R0402; tolerance: 1
R26 = RES: User Part Number: UPN; Tolerance: 1; alternate symbols: (R0402L,R0402L_ALT); part number: RES_SM-1K,E003763,1/10W,1,R0402; tolerance: 1
R27 = RES: User Part Number: UPN; Tolerance: 0.1; alternate symbols: (R0402L); part number: RES_SM-5.1K,E010267,1/16W,0.1,R0402; tolerance: 0.1
R29 = RES: User Part Number: UPN; Tolerance: 0.5; alternate symbols: (R0402L); part number: RES_SM-1MEG,E020373,1/16W,0.5,R0402; tolerance: 0.5
R30 = RES: User Part Number: UPN; Tolerance: 1; alternate symbols: (R0402L); part number: RES_SM-115K,E025179,1/10W,1,R0402; tolerance: 1
R31 = RES: User Part Number: UPN; Tolerance: 1; alternate symbols: (R0402L); part number: RES_SM-120K,E015615,1/10W,1,R0402; tolerance: 1
R33 = RES: User Part Number: UPN; Tolerance: 1; alternate symbols: (R0402L); part number: RES_SM-249K,E026055,1/16W,1,R0402; tolerance: 1
R37 R108 = RES: User Part Number: UPN; Tolerance: 5; alternate symbols: (R0603L); part number: RES_SM-220,E020960,1/4W,5,R0603; tolerance: 5
R46 = RES: User Part Number: UPN; Tolerance: 1; alternate symbols: (R0402L); part number: RES_SM-147K,E006339,1/16W,1,R0402; tolerance: 1
R48 = RES: User Part Number: UPN; Tolerance: 0.5; alternate symbols: (R0402L); part number: RES_SM-137K,E025681,1/16W,0.5,R0402; tolerance: 0.5
R49 = RES: User Part Number: UPN; Tolerance: 1; alternate symbols: (R0402L); part number: RES_SM-1.2MEG,E024939,1/16W,1,R0402; tolerance: 1
R50 = RES: User Part Number: UPN; Tolerance: 1; alternate symbols: (R0402L); part number: RES_SM-24.9K,E007443,1/16W,1,R0402; tolerance: 1
R51 = RES: User Part Number: UPN; Tolerance: 1; alternate symbols: (R0402L); part number: RES_SM-6.8K,E011558,1/10W,1,R0402; tolerance: 1
R52 = RES: User Part Number: UPN; Tolerance: 1; alternate symbols: (R0402L); part number: RES_SM-2.37MEG,E025742,1/16W,1,R0402; tolerance: 1
R53 = RES: User Part Number: UPN; Tolerance: 1; alternate symbols: (R0402L); part number: RES_SM-0,E010661,1/16W,1,R0402; tolerance: 1
R57 = RES: User Part Number: UPN; Tolerance: 1; alternate symbols: (R0402L); part number: RES_SM-14.3K,E025740,1/10W,1,R0402; tolerance: 1
R58 = RES: User Part Number: UPN; Tolerance: 1; alternate symbols: (R0402L); part number: RES_SM-93.1K,E025741,1/10W,1,R0402; tolerance: 1
R61 R64 R67 R68 = RES: User Part Number: UPN; Tolerance: 1; alternate symbols: (R0402L); part number: RES_SM-22K,E018369,1/16W,1,R0402; tolerance: 1
R66 = RES: User Part Number: UPN; Tolerance: 5; alternate symbols: (R0402L); part number: RES_SM-4.7,E021865,1/10W,5,R0402; tolerance: 5
R69 = RES: Tolerance: 5; User Part Number: UPN; alternate symbols: (); part number: RES_SM-4.7,E019116,1/20W,5,R0201; tolerance: 5
R72 R73 = RES: User Part Number: UPN; Tolerance: 1; alternate symbols: (R0402L); part number: RES_SM-45.3K,E019617,1/16W,1,R0402; tolerance: 1
R74 R82 R93 R94 = RES: User Part Number: UPN; Tolerance: 1; alternate symbols: (R0402L,R0402L_ALT); part number: RES_SM-4.7K,E008190,1/10W,1,R0402; tolerance: 1
R75 = RES: User Part Number: UPN; Tolerance: 1; alternate symbols: (R0603L); part number: RES_SM-300,E010157,1/10W,1,R0603; tolerance: 1
R78 R79 = RES: User Part Number: UPN; Tolerance: 1; alternate symbols: (R0603L); part number: RES_SM-10K,E003671,1/10W,1,R0603; tolerance: 1
R86 R87 = RES: User Part Number: UPN; Tolerance: 5; alternate symbols: (R0402L); part number: RES_SM-10K,E017176,1/10W,5,R0402; tolerance: 5
R100 = RES: User Part Number: UPN; Tolerance: 1; alternate symbols: (R0603L); part number: RES_SM-150,E003691,1/10W,1,R0603; tolerance: 1
R104 = RES: User Part Number: UPN; Tolerance: 1; alternate symbols: (R0603L); part number: RES_SM-680,E004249,1/16W,1,R0603; tolerance: 1
R110 R113 = RES: User Part Number: UPN; Tolerance: 1; alternate symbols: (R0402L); part number: RES_SM-22,E008191,1/16W,1,R0402; tolerance: 1
RT1 = RESTHERM: Tolerance: 1; User Part Number: UPN; alternate symbols: (); part number: RESTHERM_SM-100K,E029946,0.1W,1,R0603H35; tolerance: 1
S1 = SWSPDT_V2: Tolerance: N/A; User Part Number: UPN; alternate symbols: (); part number: SWSPDT_V2_SM-CAS-120TB,E012554,SWSML213W98H98; tolerance: N/A
S2 = SWSPDT: User Part Number: UPN; Tolerance: N/A; alternate symbols: (); part number: SWSPDT_TH-MS12ASW30,E026754,SWTHL500W272H280; tolerance: N/A
S3 S4 = SWSPST2PIN_V3: Tolerance: N/A; User Part Number: UPN; alternate symbols: (); part number: SWSPST2PIN_V3_SM-SKQMBBE010,E026439,SWSML236W138H197; tolerance: N/A
U1 = MN34906BL: Tolerance: N/A; User Part Number: UPN; alternate symbols: (); part number: MN34906BL_SM-MN34906BL,E023780,QFN38_7_8X7_4; tolerance: N/A
U2 = ADP2505_V2: Tolerance: N/A; User Part Number: UPN; alternate symbols: (); part number: ADP2505_V2_SM-ADP2505ACBZ,E020068,WLCSP20_A; tolerance: N/A
U3 = ADP5023: Tolerance: N/A; User Part Number: UPN; alternate symbols: (); part number: ADP5023_SM-ADP5023ACPZ,E015738,QFN24_4X4_PAD2_1X2_1; tolerance: N/A
U4 = ADDI9036: User Part Number: UPN; Tolerance: N/A; alternate symbols: (); part number: ADDI9036_SM-ADDI9036BCBZRL,E033667,WLCSP117_A; tolerance: N/A
U5 = ICAT24CM01: Tolerance: N/A; User Part Number: UPN; alternate symbols: (); part number: ICAT24CM01_SM-AT24CM01-XHM-B,E027200,TSSOP8; tolerance: N/A
U6 = ICFAN3121: Tolerance: N/A; User Part Number: UPN; alternate symbols: (); part number: ICFAN3121_SM-FAN3121TMPX,E024221,MLP8_3X3_PAD2_3X1_4; tolerance: N/A
U7 = ICFSA642: User Part Number: UPN; Tolerance: N/A; alternate symbols: (); part number: ICFSA642_SM-FSA642UMX,E033686,QFN24_3_4X2_5; tolerance: N/A
U8 U9 = ICPCA9517A: Tolerance: N/A; User Part Number: UPN; alternate symbols: (MSOP); part number: ICPCA9517A_SM-PCA9517ADMR2G,E022571,MSOP8_ALT; tolerance: N/A
U10 = ADP5071: User Part Number: UPN; Tolerance: N/A; alternate symbols: (); part number: ADP5071_SM-ADP5071ACPZ,E023943,QFN20_4X4_PAD2_6X2_6; tolerance: N/A
U12 = ADP7112: User Part Number: UPN; Tolerance: N/A; alternate symbols: (); part number: ADP7112_SM-ADP7112ACBZ-1.2-R7,E024303,WLCSP6_B; tolerance: N/A
U13 = ADT7410: Tolerance: N/A; User Part Number: UPN; alternate symbols: (); part number: ADT7410_SM-ADT7410TRZ,E010871,SO8; tolerance: N/A
Y1 = XTALOSC4P_V3: Tolerance: N/A; User Part Number: UPN; alternate symbols: (); part number: XTALOSC4P_V3_SM-45.000000MEGHZ,E025786,YSML98W79H35; tolerance: N/A

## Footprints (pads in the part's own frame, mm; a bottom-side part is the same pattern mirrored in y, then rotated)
C0201
  rect 0.305x0.406 smd: 1(-0.318,0) 2(0.318,0)
C0402
  rect 0.584x0.66 smd: 1(-0.5,0) 2(0.5,0)
C0508H28
  rect 0.66x2.134 smd: 1(-0.56,0) 2(0.56,0)
C0603
  rect 0.94x0.991 smd: 1(-0.8,0) 2(0.8,0)
C0805H53
  rect 1.295x1.6 smd: 1(-0.953,0) 2(0.953,0)
C0805H60
  rect 1.295x1.6 smd: 1(-0.953,0) 2(0.953,0)
C1206
  rect 1.143x1.803 smd: 1(-1.5,0) 2(1.5,0)
C1206H37
  rect 1.6x2.007 smd: 1(-1.397,0) 2(1.397,0)
C1206H71
  rect 1.6x2.007 smd: 1(-1.397,0) 2(1.397,0)
C1210-2
  rect 1.575x2.692 smd: 1(-1.397,0) 2(1.397,0)
C1210H106
  rect 1.092x2.057 smd: 1(-1.646,0) 2(1.646,0)
CNCUI-PJ-002A_A
  round 3.048 hole 1.803 unplated: (0,2.1)
  round 2.362 hole 1.6 unplated: (0,-2.4)
  rect 2.413x2.794 smd: 1A(-5.707,3.7) 1B(-5.707,-2.4) 2(5.707,-2.4) 3(5.707,3.7)
CNFCI61083-063402
  round 1.905 hole 0.787 unplated: (-14.1,0)
  round 2.21 hole 1.194 unplated: (14.1,0)
  rect 0.508x2.007 smd: 1(-11.6,2.197) 2(-11.6,-2.197) 3(-10.8,2.197) 4(-10.8,-2.197) 5(-10,2.197) 6(-10,-2.197) 7(-9.2,2.197) 8(-9.2,-2.197) 9(-8.4,2.197) 10(-8.4,-2.197) 11(-7.6,2.197) 12(-7.6,-2.197) 13(-6.8,2.197) 14(-6.8,-2.197) 15(-6,2.197) 16(-6,-2.197) 17(-5.2,2.197) 18(-5.2,-2.197) 19(-4.4,2.197) 20(-4.4,-2.197) 21(-3.6,2.197) 22(-3.6,-2.197) 23(-2.8,2.197) 24(-2.8,-2.197) 25(-2,2.197) 26(-2,-2.197) 27(-1.2,2.197) 28(-1.2,-2.197) 29(-0.4,2.197) 30(-0.4,-2.197) 31(0.4,2.197) 32(0.4,-2.197) 33(1.2,2.197) 34(1.2,-2.197) 35(2,2.197) 36(2,-2.197) 37(2.8,2.197) 38(2.8,-2.197) 39(3.6,2.197) 40(3.6,-2.197) 41(4.4,2.197) 42(4.4,-2.197) 43(5.2,2.197) 44(5.2,-2.197) 45(6,2.197) 46(6,-2.197) 47(6.8,2.197) 48(6.8,-2.197) 49(7.6,2.197) 50(7.6,-2.197) 51(8.4,2.197) 52(8.4,-2.197) 53(9.2,2.197) 54(9.2,-2.197) 55(10,2.197) 56(10,-2.197) 57(10.8,2.197) 58(10.8,-2.197) 59(11.6,2.197) 60(11.6,-2.197)
CNHDR2X30H202
  round 2.286 hole 1.016 unplated: (-10.063,2.667) (10.063,2.667)
  rect 0.279x2.286 smd: 1(-7.264,-2.865) 2(-7.264,2.865) 3(-6.764,-2.865) 4(-6.764,2.865) 5(-6.264,-2.865) 6(-6.264,2.865) 7(-5.763,-2.865) 8(-5.763,2.865) 9(-5.263,-2.865) 10(-5.263,2.865) 11(-4.763,-2.865) 12(-4.763,2.865) 13(-4.262,-2.865) 14(-4.262,2.865) 15(-3.762,-2.865) 16(-3.762,2.865) 17(-3.261,-2.865) 18(-3.261,2.865) 19(-2.761,-2.865) 20(-2.761,2.865) 21(-2.261,-2.865) 22(-2.261,2.865) 23(-1.76,-2.865) 24(-1.76,2.865) 25(-1.26,-2.865) 26(-1.26,2.865) 27(-0.759,-2.865) 28(-0.759,2.865) 29(-0.259,-2.865) 30(-0.259,2.865) 31(0.241,-2.865) 32(0.241,2.865) 33(0.742,-2.865) 34(0.742,2.865) 35(1.242,-2.865) 36(1.242,2.865) 37(1.742,-2.865) 38(1.742,2.865) 39(2.243,-2.865) 40(2.243,2.865) 41(2.743,-2.865) 42(2.743,2.865) 43(3.244,-2.865) 44(3.244,2.865) 45(3.744,-2.865) 46(3.744,2.865) 47(4.244,-2.865) 48(4.244,2.865) 49(4.745,-2.865) 50(4.745,2.865) 51(5.245,-2.865) 52(5.245,2.865) 53(5.745,-2.865) 54(5.745,2.865) 55(6.246,-2.865) 56(6.246,2.865) 57(6.746,-2.865) 58(6.746,2.865) 59(7.247,-2.865) 60(7.247,2.865)
  rect 2.54x0.432 smd: PAD1(-8.065,0) PAD4(8.065,0)
  rect 4.699x0.432 smd: PAD2(-3.175,0) PAD3(3.175,0)
CNSMMHDR2X20L1571W157H272
  rect 0.991x2.743 smd: 1(-19,2.129) 2(-19,-2.129) 3(-17,2.129) 4(-17,-2.129) 5(-15,2.129) 6(-15,-2.129) 7(-13,2.129) 8(-13,-2.129) 9(-11,2.129) 10(-11,-2.129) 11(-9,2.129) 12(-9,-2.129) 13(-7,2.129) 14(-7,-2.129) 15(-5,2.129) 16(-5,-2.129) 17(-3,2.129) 18(-3,-2.129) 19(-1,2.129) 20(-1,-2.129) 21(1,2.129) 22(1,-2.129) 23(3,2.129) 24(3,-2.129) 25(5,2.129) 26(5,-2.129) 27(7,2.129) 28(7,-2.129) 29(9,2.129) 30(9,-2.129) 31(11,2.129) 32(11,-2.129) 33(13,2.129) 34(13,-2.129) 35(15,2.129) 36(15,-2.129) 37(17,2.129) 38(17,-2.129) 39(19,2.129) 40(19,-2.129)
CNTE1-1734248-5
  rect 0.61x1.651 smd: 1(-7,-1.876) 2(-6,-1.876) 3(-5,-1.876) 4(-4,-1.876) 5(-3,-1.876) 6(-2,-1.876) 7(-1,-1.876) 8(0,-1.876) 9(1,-1.876) 10(2,-1.876) 11(3,-1.876) 12(4,-1.876) 13(5,-1.876) 14(6,-1.876) 15(7,-1.876)
  rect 0.61x1.854 smd: 16(7,1.876) 17(6,1.876) 18(5,1.876) 19(4,1.876) 20(3,1.876) 21(2,1.876) 22(1,1.876) 23(0,1.876) 24(-1,1.876) 25(-2,1.876) 26(-3,1.876) 27(-4,1.876) 28(-5,1.876) 29(-6,1.876) 30(-7,1.876)
DO214AC
  rect 1.778x2.159 smd: A(2.032,0) C(-2.032,0)
DSML110W70H39
  rect 0.889x1.397 smd: A(1.605,0)
  rect 2.21x1.397 smd: C(-0.945,0)
JPRSLD03
  rect 0.61x1.524 smd: 1(-0.838,0) 2(0,0) 3(0.838,0)
L0402
  rect 0.584x0.711 smd: 1(-0.475,0) 2(0.475,0)
L0603
  rect 0.94x0.991 smd: 1(-0.8,0) 2(0.8,0)
L0805
  rect 1.194x1.448 smd: 1(-0.85,0) 2(0.85,0)
L01005
  rect 0.229x0.229 smd: 1(-0.189,0) 2(0.189,0)
LED0603
  rect 0.965x0.762 smd: A(0.8,0) C(-0.8,0)
LED1206
  rect 1.499x1.499 smd: A(1.749,0) C(-1.749,0)
LSML75W79H39
  rect 1.041x2.21 smd: 1(-0.724,0) 2(0.724,0)
LSMSQ157H83_A
  rect 0.965x3.708 smd: 1(-1.181,0) 2(1.181,0)
LSMSQ157H122
  rect 0.965x3.708 smd: 1(-1.181,0) 2(1.181,0)
MLP8_3X3_PAD2_3X1_4
  oval 0.305x0.914 smd: 1(-0.975,-1.557) 2(-0.325,-1.557) 3(0.325,-1.557) 4(0.975,-1.557) 5(0.975,1.557) 6(0.325,1.557) 7(-0.325,1.557) 8(-0.975,1.557)
  rect 2.311x1.397 smd: PAD(0,0)
MSOP8_ALT
  rect 0.406x1.194 smd: 1(-0.975,-2.05) 2(-0.325,-2.05) 3(0.325,-2.05) 4(0.975,-2.05) 5(0.975,2.05) 6(0.325,2.05) 7(-0.325,2.05) 8(-0.975,2.05)
QFN20_4X4_PAD2_6X2_6
  oval 0.305x1.041 smd: 1(-1,-2.019) 2(-0.5,-2.019) 3(0,-2.019) 4(0.5,-2.019) 5(1,-2.019) 11(1,2.019) 12(0.5,2.019) 13(0,2.019) 14(-0.5,2.019) 15(-1,2.019)
  oval 1.041x0.305 smd: 6(2.019,-1) 7(2.019,-0.5) 8(2.019,0) 9(2.019,0.5) 10(2.019,1) 16(-2.019,1) 17(-2.019,0.5) 18(-2.019,0) 19(-2.019,-0.5) 20(-2.019,-1)
  rect 2.591x2.591 smd: PAD(0,0)
QFN24_3_4X2_5
  rect 0.229x0.66 smd: 1(-1,-1.07)
  rect 0.229x0.559 smd: 2(-0.6,-1.121) 3(-0.2,-1.121) 4(0.2,-1.121) 5(0.6,-1.121) 6(1,-1.121) 13(1,1.121) 14(0.6,1.121) 15(0.2,1.121) 16(-0.2,1.121) 17(-0.6,1.121) 18(-1,1.121)
  rect 0.559x0.229 smd: 7(1.57,-1) 8(1.57,-0.6) 9(1.57,-0.2) 10(1.57,0.2) 11(1.57,0.6) 12(1.57,1) 19(-1.57,1) 20(-1.57,0.6) 21(-1.57,0.2) 22(-1.57,-0.2) 23(-1.57,-0.6) 24(-1.57,-1)
QFN24_4X4_PAD2_1X2_1
  oval 0.305x0.991 smd: 1(-1.25,-2) 2(-0.75,-2) 3(-0.25,-2) 4(0.25,-2) 5(0.75,-2) 6(1.25,-2) 13(1.25,2) 14(0.75,2) 15(0.25,2) 16(-0.25,2) 17(-0.75,2) 18(-1.25,2)
  oval 0.991x0.305 smd: 7(2,-1.25) 8(2,-0.75) 9(2,-0.25) 10(2,0.25) 11(2,0.75) 12(2,1.25) 19(-2,1.25) 20(-2,0.75) 21(-2,0.25) 22(-2,-0.25) 23(-2,-0.75) 24(-2,-1.25)
  rect 2.108x2.108 smd: PAD(0,0)
QFN38_7_8X7_4
  rect 1.219x1.219 smd: 1(-3.612,-3.412) 11(3.612,-3.412) 20(3.612,3.412) 30(-3.612,3.412)
  oval 0.406x1.295 smd: 2(-2.6,-3.45) 3(-1.95,-3.45) 4(-1.3,-3.45) 5(-0.65,-3.45) 6(0,-3.45) 7(0.65,-3.45) 8(1.3,-3.45) 9(1.95,-3.45) 10(2.6,-3.45) 21(2.6,3.45) 22(1.95,3.45) 23(1.3,3.45) 24(0.65,3.45) 25(0,3.45) 26(-0.65,3.45) 27(-1.3,3.45) 28(-1.95,3.45) 29(-2.6,3.45)
  oval 1.295x0.406 smd: 12(3.65,-2.275) 13(3.65,-1.625) 14(3.65,-0.975) 15(3.65,-0.325) 16(3.65,0.325) 17(3.65,0.975) 18(3.65,1.625) 19(3.65,2.275) 31(-3.65,2.275) 32(-3.65,1.625) 33(-3.65,0.975) 34(-3.65,0.325) 35(-3.65,-0.325) 36(-3.65,-0.975) 37(-3.65,-1.625) 38(-3.65,-2.275)
R0201
  rect 0.305x0.406 smd: 1(-0.318,0) 2(0.318,0)
R0402
  rect 0.635x0.737 smd: 1(-0.5,0) 2(0.5,0)
R0603
  rect 0.787x0.991 smd: 1(-0.85,0) 2(0.85,0)
R0603H35
  rect 0.813x0.813 smd: 1(-0.907,0) 2(0.907,0)
R0805
  rect 1.041x1.397 smd: 1(-0.95,0) 2(0.95,0)
R1206
  rect 1.041x1.753 smd: 1(-1.5,0) 2(1.5,0)
SC70
  rect 0.406x0.508 smd: 1(-0.65,-0.95) 2(0,-0.95) 3(0.65,-0.95) 4(0.65,0.95) 5(0,0.95) 6(-0.65,0.95)
SO8
  rect 0.61x2.184 smd: 1(-1.905,-2.54) 2(-0.635,-2.54) 3(0.635,-2.54) 4(1.905,-2.54) 5(1.905,2.54) 6(0.635,2.54) 7(-0.635,2.54) 8(-1.905,2.54)
SOD323-4
  rect 0.635x0.838 smd: A(1.118,0) C(-1.118,0)
SOD523
  rect 0.457x0.406 smd: A(0.679,0) C(-0.679,0)
SOT-963
  rect 0.203x0.203 smd: 1(-0.35,-0.45) 2(0,-0.45) 3(0.35,-0.45) 4(0.35,0.45) 5(0,0.45) 6(-0.35,0.45)
SWSML213W98H98
  rect 0.991x1.295 smd: 1(-1.75,-1.948) 2(0,1.948) 3(1.75,-1.948)
SWSML236W138H197
  rect 1.803x1.6 smd: 1(-2.702,0) 2(2.702,0)
SWTHL500W272H280
  round 2.794 hole 1.499 unplated: (-1.905,9.525) (11.303,9.525)
  rect 2.286x2.286 hole 1.778: 1(0,0)
  round 2.286 hole 1.778: 2(4.699,0) 3(9.398,0)
TPSMC30
  round 0.762 smd: 1(0,0)
TSSOP8
  rect 0.33x1.651 smd: 1(-0.975,-2.92) 2(-0.325,-2.92) 3(0.325,-2.92) 4(0.975,-2.92) 5(0.975,2.92) 6(0.325,2.92) 7(-0.325,2.92) 8(-0.975,2.92)
unnamed#2
  round 2.489 hole 2.489 unplated: (0,0)
unnamed#3
  round 1 hole 1.45 unplated: (-8.7,0) (8.7,0)
  round 0.5 hole 1.02 unplated: (-7.4,2.5) (7.4,-2.5)
UQFN6_1_6X1_6PAD0_5X1_05
  oval 0.254x0.813 smd: 1(-0.5,-0.907) 2(0,-0.907) 3(0.5,-0.907) 4(0.5,0.907) 5(0,0.907) 6(-0.5,0.907)
  rect 1.041x0.508 smd: PAD(0,0)
WLCSP6_B
  round 0.203 smd: A1(-0.4,-0.2) A2(-0.4,0.2) B1(0,-0.2) B2(0,0.2) C1(0.4,-0.2) C2(0.4,0.2)
WLCSP20_A
  round 0.254 smd: A1(-1,-0.75) A2(-1,-0.25) A3(-1,0.25) A4(-1,0.75) B1(-0.5,-0.75) B2(-0.5,-0.25) B3(-0.5,0.25) B4(-0.5,0.75) C1(0,-0.75) C2(0,-0.25) C3(0,0.25) C4(0,0.75) D1(0.5,-0.75) D2(0.5,-0.25) D3(0.5,0.25) D4(0.5,0.75) E1(1,-0.75) E2(1,-0.25) E3(1,0.25) E4(1,0.75)
WLCSP117_A
  round 0.254 smd: A2(-2.5,-2) A3(-2.5,-1.5) A4(-2.5,-1) A5(-2.5,-0.5) A6(-2.5,0) A7(-2.5,0.5) A8(-2.5,1) A9(-2.5,1.5) A10(-2.5,2) B1(-2,-2.5) B2(-2,-2) B3(-2,-1.5) B4(-2,-1) B5(-2,-0.5) B6(-2,0) B7(-2,0.5) B8(-2,1) B9(-2,1.5) B10(-2,2) B11(-2,2.5) C1(-1.5,-2.5) C2(-1.5,-2) C3(-1.5,-1.5) C4(-1.5,-1) C5(-1.5,-0.5) C6(-1.5,0) C7(-1.5,0.5) C8(-1.5,1) C9(-1.5,1.5) C10(-1.5,2) C11(-1.5,2.5) D1(-1,-2.5) D2(-1,-2) D3(-1,-1.5) D4(-1,-1) D5(-1,-0.5) D6(-1,0) D7(-1,0.5) D8(-1,1) D9(-1,1.5) D10(-1,2) D11(-1,2.5) E1(-0.5,-2.5) E2(-0.5,-2) E3(-0.5,-1.5) E4(-0.5,-1) E5(-0.5,-0.5) E6(-0.5,0) E7(-0.5,0.5) E8(-0.5,1) E9(-0.5,1.5) E10(-0.5,2) E11(-0.5,2.5) F1(0,-2.5) F2(0,-2) F3(0,-1.5) F4(0,-1) F5(0,-0.5) F6(0,0) F7(0,0.5) F8(0,1) F9(0,1.5) F10(0,2) F11(0,2.5) G1(0.5,-2.5) G2(0.5,-2) G3(0.5,-1.5) G4(0.5,-1) G5(0.5,-0.5) G6(0.5,0) G7(0.5,0.5) G8(0.5,1) G9(0.5,1.5) G10(0.5,2) G11(0.5,2.5) H1(1,-2.5) H2(1,-2) H3(1,-1.5) H4(1,-1) H5(1,-0.5) H6(1,0) H7(1,0.5) H8(1,1) H9(1,1.5) H10(1,2) H11(1,2.5) J1(1.5,-2.5) J2(1.5,-2) J3(1.5,-1.5) J4(1.5,-1) J5(1.5,-0.5) J6(1.5,0) J7(1.5,0.5) J8(1.5,1) J9(1.5,1.5) J10(1.5,2) J11(1.5,2.5) K1(2,-2.5) K2(2,-2) K3(2,-1.5) K4(2,-1) K5(2,-0.5) K6(2,0) K7(2,0.5) K8(2,1) K9(2,1.5) K10(2,2) K11(2,2.5) L2(2.5,-2) L3(2.5,-1.5) L4(2.5,-1) L5(2.5,-0.5) L6(2.5,0) L7(2.5,0.5) L8(2.5,1) L9(2.5,1.5) L10(2.5,2)
YSML98W79H35
  rect 1.092x0.991 smd: 1(-0.921,-0.72) 2(0.921,-0.72) 3(0.921,0.72) 4(-0.921,0.72)

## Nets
5V_LD: JP3.1 P21.27 P21.29 P21.31 P21.33 P21.35 P21.37 P21.39 R16.2(N2) R39.2(N2) R95.2(N2)
5VCC: C49.2(N2) E2.2(N2) E3.1 JP6.1 JP7.1 JP8.1 R17.1 R37.2(N2) R44.1 R75.1
9VDD: C12.1 C15.1 Q1.4(E2) R9.1 R26.1 R59.2(N2) R71.2(N2) R104.1 U4.K10
GND: A1.2 A1.PAD C1.1 C2.2(N2) C3.1 C4.2(N2) C5.2(N2) C6.2(N2) C7.2(N2) C8.2(N2) C9.1 C10.2(N2) C11.2(N2) C12.2(N2) C13.2(N2) C14.2(N2) C15.2(N2) C16.2(N2) C17.2(N2) C18.2(N2) C19.2(N2) C20.1 C22.2(N2) C23.2(N2) C24.2(N2) C25.2(N2) C26.2(N2) C27.2(N2) C28.2(N2) C29.1 C30.2(N2) C31.2(N2) C32.2(N2) C33.2(N2) C34.2(N2) C35.2(N2) C38.2(N2) C39.2(N2) C40.2(N2) C41.2(N2) C42.2(N2) C43.2(N2) C44.2(N2) C45.2(N2) C46.2(N2) C47.2(N2) C48.2(N2) C49.1 C50.1 C51.2(N2) C52.2(N2) C53.1 C54.2(N2) C55.2(N2) C56.1 C57.1 C58.2(N2) C60.2(N2) C61.2(N2) C62.1 C63.1 C64.2(N2) C65.2(N2) C66.2(N2) C67.1 C68.2(N2) C69.1 C70.1 C71.2(N2) C72.2(N2) C74.2(N2) C75.2(N2) C76.2(N2) C77.1 C78.2(N2) C79.2(N2) C80.2(N2) C81.2(N2) C82.1 C83.1 C84.2(N2) C85.2(N2) D1.A(P) D6.C DS1.C DS2.C DS3.C GND7.1(N1) GND8.1(N1) JP4.3 JP5.2(COM) JP8.3 L8.1 P1.1 P1.4 P1.7 P1.10 P3.6 P3.12 P3.13 P3.18(N9) P3.19 P3.24 P3.25 P3.30 P3.31 P3.37 P3.40 P3.43 P3.46 P3.49 P3.52 P3.55 P3.58 P4.1 P4.2 P4.39 P4.40 P21.30 P21.34 P21.38 P21.42 P21.46 P21.50 P21.54 P21.58 P21.PAD1 P21.PAD2 P21.PAD3 P21.PAD4 P31.2 P31.3(N4) Q2.1 Q2.4(E) R2.1 R13.2(N2) R14.2(N2) R18.1 R20.2(N2) R23.2(N2) R25.2(N2) R27.2(N2) R29.2(N2) R36.1 R38.2(N2) R48.2(N2) R54.1 R57.2(N2) R60.1 R63.1 R73.1 R90.1 R103.1 R106.1 RT1.1 TP18.1(N1) U1.6 U1.20 U1.22 U1.24 U1.29 U2.B4 U2.C2 U2.C4 U3.1 U3.2 U3.5 U3.14 U3.18 U3.23 U3.24 U3.PAD U4.B2 U4.B3 U4.B5 U4.B7 U4.B9 U4.C2 U4.C3 U4.C5 U4.C7 U4.C9 U4.C10 U4.D2 U4.D3 U4.D6 U4.D10 U4.E2 U4.E4 U4.E9 U4.E10 U4.G2 U4.G10 U4.H10 U4.J10 U4.K2 U4.L6 U5.4 U6.4 U6.5 U6.PAD U7.9 U8.4 U9.4 U10.13 U10.19 U10.PAD U12.C2 U13.7 Y1.2
V1: U1.37 U4.J9
V2: U1.3 U4.J8
V3: U1.36 U4.H7
V4: U1.4 U4.L10
V9: U1.2 U4.J7
V10: U1.13 U4.K8
V11: U1.14 U4.H5
V12: U1.35 U4.L8
V13: U1.8 U4.K7
V14: U1.11 U4.J6
V15: U1.9 U4.K6
V16: U1.5 U4.L7
1P8VDD: C6.1 C14.1 C17.1 C19.1 C22.1 C23.1 C25.1 C28.1 C77.2(N2) C82.2(N2) C83.2(N2) D4.A(P) E1.2(N2) JP1.1 R34.2(N2) R72.2(N2) U4.A6 U4.B1 U4.B6 U4.B11 U4.E1 U4.G3 U4.H11 U4.K1 U4.L5
2P1VDD: C45.1 R32.2(N2) U3.21
3P3VDD: C10.1 C11.1 C13.1 C16.1 C26.1 C31.1 C54.1 C58.1 C60.1 C61.1 C67.2(N2) C68.1 C69.2(N2) C75.1 E5.1 P21.9 R4.2(N2) R24.1 R35.1 R65.2(N2) R74.1 R82.1 R91.2(N2) R93.2(N2) R94.2(N2) R101.2(N2) R102.2(N2) R105.2(N2) U4.A2 U4.A4 U4.A8 U4.A10 U4.D1 U4.D11 U4.E11 U4.G11 U4.J11 U8.8(VCC(B)) U9.8(VCC(B)) U13.8(VDD)
3P5VDD: C53.2(N2) JP1.3 R4.1 R22.2(N2) U4.C1
AFE_GPO1: TP6.1(N1) U1.33 U4.G9
AFE_GPO2: TP7.1(N1) U4.G8
AFE_GPO3: JP6.3 JP9.3 TP8.1(N1) U4.F3
AFE_GPO4: JP3.3 JP7.3 TP9.1(N1) U4.H4
AFE_GPO5: TP14.1(N1) U4.L4
AFE_GPO6: JP2.3 TP13.1(N1) U4.K4
AFE_GPO7: LD_EN1.2(S2) TP17.1(N1) U4.J4
AFE_GPO8: LD_EN2.2(S2) TP16.1(N1) U4.J5
AFETEMP_I2C1_SCL: R82.2(N2) U8.7 U13.1
AFETEMP_I2C1_SDA: R74.2(N2) U8.6 U13.2
CCDGNDA: JP5.3 U4.D9
CCDINA: C21.2(N2) U4.B10
CLI: R110.2(N2) U4.C6
CLK_N: U4.J3 U7.2
CLK_P: U4.J2 U7.1
DATA0_N: U4.J1 U7.4
DATA0_P: U4.H1 U7.3
DATA1_N: U4.H2 U7.6
DATA1_P: U4.H3 U7.5
H1: U1.28 U4.F10
H2: U1.27 U4.F11
HD: TP2.1(N1) U4.F2
HL: R66.1 U4.H9
I2C2_SCL: P3.32 R41.1 R43.2(N2) R98.1 TP12.1(N1)
I2C2_SDA: P3.34 R6.1 R45.2(N2) R109.1 TP11.1(N1)
IOVDD: C33.1 C52.1 C63.2(N2) C70.2(N2) JP1.2(COM) P21.15 R43.1 R45.1 R47.2(N2) R55.2(N2) R61.2(N2) R62.2(N2) R64.2(N2) R67.2(N2) R68.2(N2) R77.1 R80.1 R86.1 R87.1 U4.G1 U5.8 U8.1 U9.1
LASERTEMP_I2C1_SCL: P21.5 R94.1 U9.7
LASERTEMP_I2C1_SDA: P21.7 R93.1 U9.6
LD1: LD1.1(N1) P21.60 U4.A3
LD2: LD2.1(N1) P21.52 U4.A5
LD3: LD3.1(N1) P21.44 U4.A7
LD4: LD4.1(N1) P21.36 U4.A9
LD5: R5.1 U4.C11
LD_EN1: LD_EN1.1 P21.1
LD_EN2: LD_EN2.1 P21.3
LED_BLUE: P4.8 R78.1
LED_RED: P4.10 R79.1
LS_I2C0_SCL: P4.15 R61.1 U5.6
LS_I2C0_SDA: P4.17 R64.1 U5.5
LS_I2C1_SCL: P4.19 R68.1 U8.2 U9.2
LS_I2C1_SDA: P4.21 R67.1 U8.3 U9.3
MIPI_CSI1_CLK_M: P3.56 U7.16
MIPI_CSI1_CLK_P: P3.54 U7.17
MIPI_CSI1_DATA0_M: P3.44 U7.14
MIPI_CSI1_DATA0_P: P3.42 U7.15
MIPI_CSI1_DATA1_M: P3.50 U7.12
MIPI_CSI1_DATA1_P: P3.48 U7.13
REFB: C8.1 U4.D8
REFT: C2.1 U4.D7
RG: R69.1 U4.H8
RPI_CLKN: P1.8 U7.23
RPI_CLKP: P1.9(N9) U7.22
RPI_DATA0N: P1.2 U7.21
RPI_DATA0P: P1.3 U7.20
RPI_DATA1N: P1.5 U7.18
RPI_DATA1P: P1.6 U7.19
RSTB_SYNC: C24.1 P4.23 TP3.1(N1) U4.G4
SPI1_CLK: R28.1 R113.1 TP15.1(N1)
SPI1_CS_N: P3.7 R89.2(N2) TP10.1(N1)
SPI1_MISO: P3.1 R88.2(N2) TP4.1(N1)
SPI1_MOSI: P3.11 R3.1 TP5.1(N1)
SUB: C59.2(N2) D4.C D5.C R29.1 R42.1 U1.15 U1.16
SUBOUT: R7.1 U1.18
TAL1: P21.56 TAL1.1(N1) U4.C4
TAL2: P21.48 TAL2.1(N1) U4.B4
TAL3: P21.40 TAL3.1(N1) U4.B8
TAL4: P21.32 TAL4.1(N1) U4.C8
TAL5: R40.1 R42.2(N2) U4.E8
TAVDD: C7.1 R65.1 U4.E6
TEMP_CT_AFE: P4.24 R87.2(N2) U13.6
TEMP_CT_LASER: P4.25 P21.11
TEMP_INT_AFE: P4.26 R86.2(N2) U13.5
TEMP_INT_LASER: P4.27 P21.13
UNNAMED_5_ADP2505V2_I467_BSTA: C36.2(N2) U2.A1
UNNAMED_5_ADP2505V2_I467_BSTB: C37.1 U2.E2
UNNAMED_5_ADP2505V2_I467_CM: C35.1 R13.1 U2.E1
UNNAMED_5_ADP2505V2_I467_EN: JP3.2(COM) R14.1 U2.C3
UNNAMED_5_ADP2505V2_I467_FB: R12.2(N2) R25.1 U2.D1
UNNAMED_5_ADP2505V2_I467_PGN: R15.1 U2.B2
UNNAMED_5_ADP2505V2_I467_SWA1: C36.1 L1.2(N2) U2.A2 U2.B3
UNNAMED_5_ADP2505V2_I467_SWB1: C37.2(N2) L1.1 U2.D3 U2.E3
UNNAMED_5_ADP2505V2_I467_VDR: C40.1 R15.2(N2) U2.D2
UNNAMED_5_ADP2505V2_I467_VIN1: C38.1 C39.1 R16.1 U2.A3 U2.A4
UNNAMED_5_ADP2505V2_I467_VOUT1: C32.1 C34.1 R11.2(N2) R12.1 U2.D4 U2.E4(VOUT_2)
UNNAMED_5_ADP5023_I567_AVIN: C3.2(N2) C4.1 C9.2(N2) JP4.1 R17.2(N2) U3.3 U3.7 U3.12 U3.16 U3.17 U3.22
UNNAMED_5_ADP5023_I567_FB1: R23.1 R30.1 U3.11
UNNAMED_5_ADP5023_I567_FB2: R20.1 R21.1 U3.8
UNNAMED_5_ADP5023_I567_FB3: R18.2(N2) R19.1 U3.19
UNNAMED_5_ADP5023_I567_MODE: JP4.2(COM) U3.13
UNNAMED_5_ADP5023_I567_SW1: L2.2(N2) U3.15
UNNAMED_5_ADP5023_I567_SW2: L3.2(N2) U3.4
UNNAMED_5_ADP5023_I567_VOUT1: C48.1 L2.1 R22.1 R30.2(N2) U3.10
UNNAMED_5_ADP5023_I567_VOUT2: C47.1 L3.1 R21.2(N2) R32.1 U3.9
UNNAMED_5_ADP5023_I567_VOUT3: C46.1 R19.2(N2) R34.1 U3.20(VOUT3)
UNNAMED_5_ADP5071_I420_COMP1: R50.1 U10.6
UNNAMED_5_ADP5071_I420_COMP2: R51.1 U10.10
UNNAMED_5_ADP5071_I420_EN1: JP7.2(COM) U10.7
UNNAMED_5_ADP5071_I420_EN2: JP6.2(COM) U10.9
UNNAMED_5_ADP5071_I420_FB1: R48.1 R52.1 U10.5
UNNAMED_5_ADP5071_I420_FB2: R46.2(N2) R49.1 U10.11
UNNAMED_5_ADP5071_I420_INBK: L9.1 U10.1
UNNAMED_5_ADP5071_I420_PVIN1: C41.1 R44.2(N2) U10.15 U10.16 U10.17
UNNAMED_5_ADP5071_I420_SW1: D9.A(P) L9.2(N2) U10.20
UNNAMED_5_ADP5071_I420_SW2: D8.C L8.2(N2) U10.18
UNNAMED_5_ADP5071_I420_SYNC: JP8.2(COM) U10.2
UNNAMED_5_ADP5071_I420_VREF: C43.1 R46.1 U10.12
UNNAMED_5_ADP5071_I420_VREG: C66.1 U10.14(VREG)
UNNAMED_5_ADP7112_I458_EN: JP9.2(COM) R38.1 U12.C1
UNNAMED_5_ADP7112_I458_SENSE: R57.1 R58.1 U12.B2
UNNAMED_5_ADP7112_I458_SS: C80.1 U12.B1
UNNAMED_5_ADP7112_I458_VIN: C79.1 R56.2(N2) U12.A1
UNNAMED_5_ADP7112_I458_VOUT: C81.1 R58.2(N2) R59.1 U12.A2(VOUT)
UNNAMED_5_CAP_I59_N2: C50.2(N2) E3.2(N2) R95.1
UNNAMED_5_CAP_I499_N1: C71.1 D8.A(P) E4.1 R49.2(N2)
UNNAMED_5_CAP_I500_N1: C78.1 D9.C R8.1 R52.2(N2)
UNNAMED_5_CAP_I511_N1: C42.1 E2.1 R100.2(N2) S2.2
UNNAMED_5_CAP_I516_N1: C72.1 R50.2(N2)
UNNAMED_5_CAP_I517_N1: C74.1 R51.2(N2)
UNNAMED_5_CN4PV6_I401_N1: D1.C P31.1A P31.1B S2.1
UNNAMED_5_DIOLED_I652_P: DS1.A(P) R100.1
UNNAMED_5_DIOLED_I662_P: DS2.A(P) R104.2(N2)
UNNAMED_5_DIOLED_I665_P: DS3.A(P) R108.1
UNNAMED_5_FERRITE_I642_N2: E4.2(N2) R53.1
UNNAMED_7_ADA4800PRELIM_I10_IDR: A1.4 C65.1 R33.1
UNNAMED_7_ADA4800PRELIM_I10_IN: A1.1 U1.21(VO)
UNNAMED_7_ADA4800PRELIM_I10_ISF: A1.6 C29.2(N2) R31.1
UNNAMED_7_ADA4800PRELIM_I10_OUT: A1.3 R76.1
UNNAMED_7_ADA4800PRELIM_I10_VPO: A1.5(V_POS) C62.2(N2) R9.2(N2) R31.2(N2) R33.2(N2)
UNNAMED_7_CAP_I99_N1: C30.1 D5.A(P) Q1.1 Q1.3 R27.1
UNNAMED_7_CAP_I107_N1: C18.1 Q1.2 R7.2(N2)
UNNAMED_7_CAP_I131_N1: C51.1 D6.A(P) R70.1 U1.30
UNNAMED_7_CAP_I133_N1: C73.1 R69.2(N2)
UNNAMED_7_CAP_I133_N2: C73.2(N2) U1.23
UNNAMED_7_CAP_I138_N1: C59.1 R40.2(N2) U6.6 U6.7
UNNAMED_7_CAP_I142_N1: C76.1 R71.1 U1.19
UNNAMED_7_CAP_I150_N1: C21.1 JP5.1 R76.2(N2)
UNNAMED_7_ICFAN3121_I89_EN: JP2.2(COM) U6.3
UNNAMED_7_ICFAN3121_I89_IN: R5.2(N2) U6.2
UNNAMED_7_MN34906BL_I91_HL: R66.2(N2) U1.17
UNNAMED_7_RES_I93_N2: Q1.5 Q1.6 R26.2(N2)
UNNAMED_10_ADDI9036_I362_AUXINA: C57.2(N2) R72.1 R73.2(N2) RT1.2(N2) U4.E7
UNNAMED_10_ADDI9036_I362_DNC3: R89.1 U4.E3
UNNAMED_10_ADDI9036_I362_DNC4: R88.1 U4.F4
UNNAMED_10_ADDI9036_I362_I2CSCL: R28.2(N2) R41.2(N2) U4.G5
UNNAMED_10_ADDI9036_I362_I2CSDA: R3.2(N2) R6.2(N2) U4.F5
UNNAMED_10_ADDI9036_I362_MTEST: R2.2(N2) U4.K3
UNNAMED_10_FERRITE_I381_N1: C5.1 E1.1 R1.2(N2) Y1.4(VDD)
UNNAMED_10_ICAT24CM01_I285_A2: R47.1 R54.2(N2) U5.3
UNNAMED_10_ICAT24CM01_I285_WP: R55.1 R60.2(N2) U5.7(WP)
UNNAMED_10_RES_I124_N1: R1.1 Y1.1
UNNAMED_10_RES_I290_N1: R62.1 R63.2(N2) U5.2
UNNAMED_10_RES_I374_N1: R110.1 Y1.3
UNNAMED_12_ADT7410_I24_A0: R105.1 R106.2(N2) U13.3
UNNAMED_12_ADT7410_I24_A1: R102.1 R103.2(N2) U13.4
UNNAMED_12_CAP_I106_N2: C1.2(N2) C56.2(N2) E5.2(N2) U7.10(VCC)
UNNAMED_12_CN30PV2_I137_N13: P1.13 R98.2(N2)
UNNAMED_12_CN30PV2_I137_N14: P1.14 R109.2(N2)
UNNAMED_12_CN30PV2_I137_N15: P1.15 R35.2(N2)
UNNAMED_12_CN40PV2_I59_N15: C84.1 P4.29 S3.2(B)
UNNAMED_12_CN40PV2_I60_N14: C85.1 P4.28 S4.1
UNNAMED_12_CN60PODDEVEN_I121_N5: P3.9 R113.2(N2)
UNNAMED_12_DIOLED_I181_N: DS4.C Q2.6
